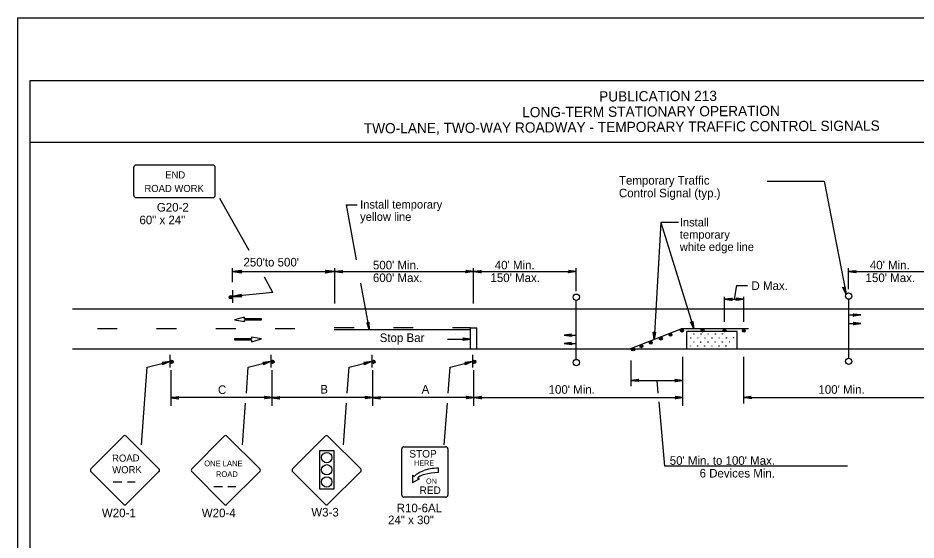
# Model space of a CAD drawing. Extents: x -14145 to -13521, y 30244 to 30661.
# Drawn here: x -13790.17 to -13768.22, y 30356.56 to 30369.31 of the extents above; entities that cross this region are included whole.
import ezdxf

# ---------------------------------------------------------------- set-up
doc = ezdxf.new("R2010")
doc.units = 0
for name, color, linetype in [('1', 7, 'Continuous'), ('10', 7, 'Continuous'), ('2', 7, 'Continuous'), ('3', 7, 'Continuous'), ('4', 7, 'Continuous'), ('61', 7, 'Continuous')]:
    doc.layers.add(name, color=color, linetype=linetype)

msp = doc.modelspace()

# ---------------------------------------------------------------- linework, layer by layer
at = {"layer": '1'}
for p, q in [((-13787.346, 30365.663), (-13787.346, 30364.975)), ((-13785.412, 30365.714), (-13787.285, 30365.714)), ((-13785.412, 30365.714), (-13787.285, 30365.714)), ((-13785.351, 30364.975), (-13785.351, 30365.663)), ((-13771.862, 30365.323), (-13770.471, 30365.323)), ((-13770.471, 30365.323), (-13769.935, 30362.561)), ((-13787.285, 30364.923), (-13785.412, 30364.923)), ((-13784.521, 30363.629), (-13785.238, 30364.895)), ((-13782.158, 30364.743), (-13781.887, 30364.743)), ((-13782.156, 30364.743), (-13781.907, 30363.402)), ((-13774.465, 30364.313), (-13774.625, 30361.456)), ((-13774.033, 30364.313), (-13774.465, 30364.313)), ((-13774.465, 30364.313), (-13773.652, 30361.715)), ((-13784.932, 30362.853), (-13784.932, 30363.195)), ((-13784.932, 30363.113), (-13782.429, 30363.113)), ((-13782.429, 30362.333), (-13782.429, 30363.195)), ((-13782.429, 30363.113), (-13779.041, 30363.113)), ((-13779.041, 30362.333), (-13779.041, 30363.195)), ((-13779.041, 30363.113), (-13776.529, 30363.113)), ((-13776.528, 30362.638), (-13776.528, 30363.194)), ((-13769.873, 30362.686), (-13769.873, 30363.195)), ((-13769.873, 30363.113), (-13767.361, 30363.113)), ((-13783.943, 30362.606), (-13784.152, 30362.976)), ((-13781.801, 30362.834), (-13781.589, 30361.693)), ((-13784.932, 30362.66), (-13784.932, 30362.348)), ((-13783.943, 30362.606), (-13784.932, 30362.504)), ((-13772.615, 30362.774), (-13772.671, 30362.436)), ((-13772.615, 30362.774), (-13772.345, 30362.774)), ((-13772.906, 30361.885), (-13772.906, 30362.5)), ((-13772.906, 30362.436), (-13772.436, 30362.436)), ((-13772.436, 30361.885), (-13772.436, 30362.5)), ((-13788.844, 30362.207), (-13759.76, 30362.207)), ((-13784.638, 30362.004), (-13784.88, 30361.938)), ((-13784.88, 30361.938), (-13784.636, 30361.892)), ((-13784.638, 30361.959), (-13784.638, 30362.004)), ((-13784.222, 30361.959), (-13784.638, 30361.959)), ((-13784.636, 30361.892), (-13784.636, 30361.937)), ((-13784.636, 30361.937), (-13784.222, 30361.937)), ((-13784.222, 30361.937), (-13784.222, 30361.959)), ((-13787.746, 30361.715), (-13788.232, 30361.715)), ((-13786.299, 30361.715), (-13786.785, 30361.715)), ((-13784.852, 30361.715), (-13785.338, 30361.715)), ((-13783.405, 30361.715), (-13783.891, 30361.715)), ((-13781.958, 30361.737), (-13782.444, 30361.737)), ((-13780.511, 30361.737), (-13780.997, 30361.737)), ((-13779.113, 30361.737), (-13779.55, 30361.737)), ((-13779.113, 30361.228), (-13779.113, 30361.737)), ((-13779.113, 30361.737), (-13778.957, 30361.737)), ((-13778.957, 30361.228), (-13778.957, 30361.737)), ((-13775.217, 30361.223), (-13773.965, 30361.715)), ((-13772.318, 30361.715), (-13773.965, 30361.715)), ((-13784.222, 30361.467), (-13784.466, 30361.514)), ((-13784.466, 30361.514), (-13784.466, 30361.468)), ((-13779.113, 30361.693), (-13782.442, 30361.693)), ((-13772.598, 30361.649), (-13773.822, 30361.649)), ((-13773.822, 30361.223), (-13773.822, 30361.649)), ((-13772.598, 30361.223), (-13772.598, 30361.649)), ((-13784.466, 30361.468), (-13784.88, 30361.468)), ((-13784.88, 30361.468), (-13784.88, 30361.446)), ((-13784.88, 30361.446), (-13784.463, 30361.446)), ((-13784.463, 30361.401), (-13784.222, 30361.467)), ((-13784.463, 30361.446), (-13784.463, 30361.401)), ((-13779.678, 30361.462), (-13779.113, 30361.462)), ((-13788.844, 30361.223), (-13759.76, 30361.223)), ((-13786.459, 30361.084), (-13786.459, 30360.772)), ((-13783.993, 30361.084), (-13783.993, 30360.772)), ((-13783.993, 30361.084), (-13783.993, 30360.772)), ((-13781.527, 30361.084), (-13781.527, 30360.772)), ((-13781.527, 30361.084), (-13781.527, 30360.772)), ((-13779.061, 30361.084), (-13779.061, 30360.772)), ((-13779.061, 30361.084), (-13779.061, 30360.772)), ((-13787.012, 30360.777), (-13786.465, 30360.917)), ((-13784.546, 30360.777), (-13783.999, 30360.917)), ((-13782.08, 30360.777), (-13781.533, 30360.917)), ((-13779.614, 30360.777), (-13779.067, 30360.917)), ((-13775.184, 30360.314), (-13775.184, 30360.94)), ((-13773.923, 30359.835), (-13773.923, 30361.029)), ((-13772.436, 30359.889), (-13772.436, 30361.035)), ((-13787.151, 30358.886), (-13787.012, 30360.777)), ((-13786.429, 30359.835), (-13786.429, 30360.709)), ((-13784.592, 30360.143), (-13784.546, 30360.777)), ((-13783.963, 30359.835), (-13783.963, 30360.709)), ((-13782.126, 30360.143), (-13782.08, 30360.777)), ((-13781.497, 30359.835), (-13781.497, 30360.709)), ((-13779.66, 30360.143), (-13779.614, 30360.777)), ((-13779.031, 30359.835), (-13779.031, 30360.709)), ((-13775.184, 30360.455), (-13773.929, 30360.455)), ((-13783.963, 30360.039), (-13786.429, 30360.039)), ((-13781.497, 30360.039), (-13783.963, 30360.039)), ((-13779.031, 30360.039), (-13781.497, 30360.039)), ((-13779.031, 30360.039), (-13773.923, 30360.039)), ((-13772.436, 30360.039), (-13767.328, 30360.039)), ((-13784.685, 30358.886), (-13784.61, 30359.9)), ((-13782.219, 30358.886), (-13782.144, 30359.9)), ((-13779.753, 30358.886), (-13779.678, 30359.9)), ((-13787.597, 30359.096), (-13788.392, 30358.293)), ((-13786.728, 30358.293), (-13787.531, 30359.096)), ((-13785.131, 30359.096), (-13785.926, 30358.293)), ((-13784.262, 30358.293), (-13785.065, 30359.096)), ((-13782.665, 30359.096), (-13783.46, 30358.293)), ((-13781.796, 30358.293), (-13782.599, 30359.096)), ((-13782.799, 30357.803), (-13782.799, 30358.741)), ((-13782.799, 30358.741), (-13782.457, 30358.741)), ((-13782.457, 30358.741), (-13782.457, 30357.803)), ((-13780.794, 30357.651), (-13780.794, 30358.787)), ((-13780.739, 30358.834), (-13779.721, 30358.834)), ((-13779.667, 30358.787), (-13779.667, 30357.651)), ((-13788.392, 30358.227), (-13787.597, 30357.432)), ((-13787.531, 30357.432), (-13786.728, 30358.227)), ((-13785.926, 30358.227), (-13785.131, 30357.432)), ((-13785.065, 30357.432), (-13784.262, 30358.227)), ((-13783.46, 30358.227), (-13782.665, 30357.432)), ((-13782.599, 30357.432), (-13781.796, 30358.227)), ((-13779.896, 30358.206), (-13779.898, 30358.317)), ((-13787.843, 30357.979), (-13787.633, 30357.979)), ((-13787.5, 30357.979), (-13787.307, 30357.979)), ((-13780.531, 30358.134), (-13780.531, 30357.963)), ((-13780.486, 30358.112), (-13780.531, 30358.134)), ((-13780.531, 30357.963), (-13780.36, 30358.049)), ((-13780.36, 30358.049), (-13780.407, 30358.072)), ((-13785.388, 30357.863), (-13785.177, 30357.863)), ((-13785.045, 30357.863), (-13784.852, 30357.863)), ((-13782.457, 30357.803), (-13782.799, 30357.803)), ((-13779.721, 30357.604), (-13780.739, 30357.604))]:
    msp.add_line(p, q, dxfattribs=at)
for points in [[(-13782.255, 30363.089), (-13782.261, 30363.101), (-13782.429, 30363.113), (-13782.255, 30363.089), (-13782.243, 30363.083), (-13782.429, 30363.113), (-13782.261, 30363.119), (-13782.255, 30363.131), (-13782.429, 30363.113), (-13782.243, 30363.143), (-13782.255, 30363.131)], [(-13779.221, 30363.137), (-13779.215, 30363.125), (-13779.041, 30363.113), (-13779.221, 30363.137), (-13779.227, 30363.143), (-13779.041, 30363.113), (-13779.215, 30363.107), (-13779.221, 30363.095), (-13779.041, 30363.113), (-13779.227, 30363.083), (-13779.221, 30363.095)], [(-13778.867, 30363.089), (-13778.873, 30363.101), (-13779.041, 30363.113), (-13778.867, 30363.089), (-13778.855, 30363.083), (-13779.041, 30363.113), (-13778.873, 30363.119), (-13778.867, 30363.131), (-13779.041, 30363.113), (-13778.855, 30363.143), (-13778.867, 30363.131)], [(-13776.709, 30363.137), (-13776.703, 30363.125), (-13776.529, 30363.113), (-13776.709, 30363.137), (-13776.715, 30363.143), (-13776.529, 30363.113), (-13776.703, 30363.107), (-13776.709, 30363.095), (-13776.529, 30363.113), (-13776.715, 30363.083), (-13776.709, 30363.095)], [(-13769.699, 30363.089), (-13769.705, 30363.101), (-13769.873, 30363.113), (-13769.699, 30363.089), (-13769.687, 30363.083), (-13769.873, 30363.113), (-13769.705, 30363.119), (-13769.699, 30363.131), (-13769.873, 30363.113), (-13769.687, 30363.143), (-13769.699, 30363.131)], [(-13769.971, 30362.739), (-13769.982, 30362.726), (-13769.935, 30362.561), (-13769.971, 30362.739), (-13769.966, 30362.746), (-13769.935, 30362.561), (-13770, 30362.719), (-13770.013, 30362.725), (-13769.935, 30362.561), (-13770.025, 30362.729), (-13770.013, 30362.725)], [(-13772.732, 30362.412), (-13772.738, 30362.424), (-13772.906, 30362.436), (-13772.732, 30362.412), (-13772.72, 30362.406), (-13772.906, 30362.436), (-13772.738, 30362.442), (-13772.732, 30362.454), (-13772.906, 30362.436), (-13772.72, 30362.466), (-13772.732, 30362.454)], [(-13772.616, 30362.46), (-13772.61, 30362.448), (-13772.436, 30362.436), (-13772.616, 30362.46), (-13772.622, 30362.466), (-13772.436, 30362.436), (-13772.61, 30362.43), (-13772.616, 30362.418), (-13772.436, 30362.436), (-13772.622, 30362.406), (-13772.616, 30362.418)], [(-13769.752, 30362.077), (-13769.74, 30362.059), (-13769.572, 30362.053), (-13769.752, 30362.077), (-13769.758, 30362.083), (-13769.572, 30362.053), (-13769.74, 30362.047), (-13769.746, 30362.029), (-13769.572, 30362.053), (-13769.758, 30362.023), (-13769.746, 30362.029)], [(-13781.64, 30361.861), (-13781.627, 30361.856), (-13781.589, 30361.693), (-13781.64, 30361.861), (-13781.649, 30361.863), (-13781.589, 30361.693), (-13781.608, 30361.857), (-13781.599, 30361.869), (-13781.589, 30361.693), (-13781.592, 30361.876), (-13781.599, 30361.869)], [(-13773.683, 30361.887), (-13773.694, 30361.875), (-13773.652, 30361.715), (-13773.683, 30361.887), (-13773.679, 30361.892), (-13773.652, 30361.715), (-13773.711, 30361.868), (-13773.724, 30361.874), (-13773.652, 30361.715), (-13773.735, 30361.877), (-13773.724, 30361.874)], [(-13769.752, 30361.873), (-13769.74, 30361.855), (-13769.572, 30361.849), (-13769.752, 30361.873), (-13769.758, 30361.879), (-13769.572, 30361.849), (-13769.74, 30361.843), (-13769.746, 30361.825), (-13769.572, 30361.849), (-13769.758, 30361.819), (-13769.746, 30361.825)], [(-13779.294, 30361.484), (-13779.285, 30361.469), (-13779.113, 30361.462), (-13779.294, 30361.484), (-13779.298, 30361.491), (-13779.113, 30361.462), (-13779.283, 30361.45), (-13779.293, 30361.44), (-13779.113, 30361.462), (-13779.301, 30361.429), (-13779.293, 30361.44)], [(-13776.647, 30361.54), (-13776.659, 30361.552), (-13776.827, 30361.558), (-13776.647, 30361.54), (-13776.641, 30361.528), (-13776.827, 30361.558), (-13776.659, 30361.57), (-13776.653, 30361.582), (-13776.827, 30361.558), (-13776.641, 30361.588), (-13776.653, 30361.582)], [(-13774.594, 30361.628), (-13774.608, 30361.62), (-13774.625, 30361.456), (-13774.594, 30361.628), (-13774.588, 30361.631), (-13774.625, 30361.456), (-13774.627, 30361.62), (-13774.637, 30361.63), (-13774.625, 30361.456), (-13774.646, 30361.637), (-13774.637, 30361.63)], [(-13776.647, 30361.336), (-13776.659, 30361.348), (-13776.827, 30361.354), (-13776.647, 30361.336), (-13776.641, 30361.324), (-13776.827, 30361.354), (-13776.659, 30361.366), (-13776.653, 30361.378), (-13776.827, 30361.354), (-13776.641, 30361.384), (-13776.653, 30361.378)], [(-13786.645, 30360.893), (-13786.633, 30360.881), (-13786.465, 30360.917), (-13786.645, 30360.893), (-13786.651, 30360.899), (-13786.465, 30360.917), (-13786.627, 30360.863), (-13786.633, 30360.851), (-13786.465, 30360.917), (-13786.639, 30360.839), (-13786.633, 30360.851)], [(-13784.179, 30360.893), (-13784.167, 30360.881), (-13783.999, 30360.917), (-13784.179, 30360.893), (-13784.185, 30360.899), (-13783.999, 30360.917), (-13784.161, 30360.863), (-13784.167, 30360.851), (-13783.999, 30360.917), (-13784.173, 30360.839), (-13784.167, 30360.851)], [(-13781.713, 30360.893), (-13781.701, 30360.881), (-13781.533, 30360.917), (-13781.713, 30360.893), (-13781.719, 30360.899), (-13781.533, 30360.917), (-13781.695, 30360.863), (-13781.701, 30360.851), (-13781.533, 30360.917), (-13781.707, 30360.839), (-13781.701, 30360.851)], [(-13779.247, 30360.893), (-13779.235, 30360.881), (-13779.067, 30360.917), (-13779.247, 30360.893), (-13779.253, 30360.899), (-13779.067, 30360.917), (-13779.229, 30360.863), (-13779.235, 30360.851), (-13779.067, 30360.917), (-13779.241, 30360.839), (-13779.235, 30360.851)], [(-13775.004, 30360.437), (-13775.016, 30360.449), (-13775.184, 30360.455), (-13775.004, 30360.437), (-13774.998, 30360.425), (-13775.184, 30360.455), (-13775.016, 30360.467), (-13775.01, 30360.479), (-13775.184, 30360.455), (-13774.998, 30360.485), (-13775.01, 30360.479)], [(-13774.525, 30360.141), (-13774.553, 30360.455)], [(-13774.109, 30360.479), (-13774.097, 30360.461), (-13773.929, 30360.455), (-13774.109, 30360.479), (-13774.115, 30360.485), (-13773.929, 30360.455), (-13774.097, 30360.449), (-13774.103, 30360.431), (-13773.929, 30360.455), (-13774.115, 30360.425), (-13774.103, 30360.431)], [(-13786.249, 30360.009), (-13786.255, 30360.021), (-13786.429, 30360.033), (-13786.249, 30360.009), (-13786.243, 30360.003), (-13786.429, 30360.033), (-13786.255, 30360.039), (-13786.249, 30360.051), (-13786.429, 30360.033), (-13786.243, 30360.063), (-13786.249, 30360.051)], [(-13784.143, 30360.063), (-13784.137, 30360.045), (-13783.963, 30360.039), (-13784.143, 30360.063), (-13784.149, 30360.069), (-13783.963, 30360.039), (-13784.137, 30360.033), (-13784.143, 30360.015), (-13783.963, 30360.039), (-13784.149, 30360.009), (-13784.143, 30360.015)], [(-13783.783, 30360.009), (-13783.789, 30360.021), (-13783.963, 30360.033), (-13783.783, 30360.009), (-13783.777, 30360.003), (-13783.963, 30360.033), (-13783.789, 30360.039), (-13783.783, 30360.051), (-13783.963, 30360.033), (-13783.777, 30360.063), (-13783.783, 30360.051)], [(-13781.677, 30360.063), (-13781.671, 30360.045), (-13781.497, 30360.039), (-13781.677, 30360.063), (-13781.683, 30360.069), (-13781.497, 30360.039), (-13781.671, 30360.033), (-13781.677, 30360.015), (-13781.497, 30360.039), (-13781.683, 30360.009), (-13781.677, 30360.015)], [(-13781.317, 30360.009), (-13781.323, 30360.021), (-13781.497, 30360.033), (-13781.317, 30360.009), (-13781.311, 30360.003), (-13781.497, 30360.033), (-13781.323, 30360.039), (-13781.317, 30360.051), (-13781.497, 30360.033), (-13781.311, 30360.063), (-13781.317, 30360.051)], [(-13779.211, 30360.063), (-13779.205, 30360.045), (-13779.031, 30360.039), (-13779.211, 30360.063), (-13779.217, 30360.069), (-13779.031, 30360.039), (-13779.205, 30360.033), (-13779.211, 30360.015), (-13779.031, 30360.039), (-13779.217, 30360.009), (-13779.211, 30360.015)], [(-13778.857, 30360.015), (-13778.863, 30360.027), (-13779.031, 30360.039), (-13778.857, 30360.015), (-13778.845, 30360.009), (-13779.031, 30360.039), (-13778.863, 30360.045), (-13778.857, 30360.057), (-13779.031, 30360.039), (-13778.845, 30360.069), (-13778.857, 30360.057)], [(-13774.103, 30360.063), (-13774.091, 30360.045), (-13773.923, 30360.039), (-13774.103, 30360.063), (-13774.109, 30360.069), (-13773.923, 30360.039), (-13774.091, 30360.033), (-13774.097, 30360.015), (-13773.923, 30360.039), (-13774.109, 30360.009), (-13774.097, 30360.015)], [(-13772.256, 30360.021), (-13772.268, 30360.033), (-13772.436, 30360.039), (-13772.256, 30360.021), (-13772.25, 30360.009), (-13772.436, 30360.039), (-13772.268, 30360.051), (-13772.262, 30360.063), (-13772.436, 30360.039), (-13772.25, 30360.069), (-13772.262, 30360.063)], [(-13769.902, 30358.359), (-13774.365, 30358.359), (-13774.506, 30359.936)]]:
    msp.add_lwpolyline(points, dxfattribs=at)
for centre, radius in [((-13784.973, 30362.487), 0.0408), ((-13774.462, 30361.479), 0.038), ((-13774.463, 30361.475), 0.0155), ((-13774.225, 30361.569), 0.0346), ((-13774.224, 30361.565), 0.0101), ((-13773.943, 30361.673), 0.037), ((-13773.943, 30361.673), 0.037), ((-13773.946, 30361.671), 0.0172), ((-13773.946, 30361.671), 0.0172), ((-13773.731, 30361.489), 0.00272), ((-13773.651, 30361.587), 0.00272), ((-13773.556, 30361.491), 0.00272), ((-13773.479, 30361.588), 0.00272), ((-13773.443, 30361.673), 0.037), ((-13773.446, 30361.671), 0.0172), ((-13773.385, 30361.489), 0.00272), ((-13773.304, 30361.589), 0.00272), ((-13773.209, 30361.491), 0.00272), ((-13773.13, 30361.588), 0.00272), ((-13773.035, 30361.49), 0.00272), ((-13772.958, 30361.59), 0.00272), ((-13772.904, 30361.675), 0.0353), ((-13772.9, 30361.676), 0.014), ((-13772.863, 30361.495), 0.00272), ((-13772.862, 30361.492), 0.00272), ((-13772.783, 30361.593), 0.00272), ((-13772.688, 30361.497), 0.00272), ((-13772.435, 30361.667), 0.0331), ((-13772.436, 30361.668), 0.012), ((-13774.935, 30361.291), 0.037), ((-13774.934, 30361.289), 0.0194), ((-13774.708, 30361.378), 0.036), ((-13774.711, 30361.384), 0.0161), ((-13773.736, 30361.294), 0.00272), ((-13773.656, 30361.391), 0.00272), ((-13773.561, 30361.295), 0.00272), ((-13773.485, 30361.391), 0.00272), ((-13773.388, 30361.295), 0.00272), ((-13773.308, 30361.392), 0.00272), ((-13773.214, 30361.296), 0.00272), ((-13773.135, 30361.392), 0.00272), ((-13773.041, 30361.297), 0.00272), ((-13772.96, 30361.393), 0.00272), ((-13772.869, 30361.3), 0.00272), ((-13772.867, 30361.297), 0.00272), ((-13772.789, 30361.397), 0.00272), ((-13772.694, 30361.301), 0.00272), ((-13775.137, 30361.213), 0.0379), ((-13775.136, 30361.213), 0.014), ((-13786.419, 30360.911), 0.0408), ((-13783.953, 30360.911), 0.0408), ((-13781.487, 30360.911), 0.0408), ((-13779.021, 30360.911), 0.0408), ((-13782.628, 30358.57), 0.126), ((-13782.628, 30358.272), 0.126), ((-13782.628, 30357.975), 0.126)]:
    msp.add_circle(centre, radius, dxfattribs=at)
for centre, radius, start, end in [((-13784.968, 30362.495), 0.0214, 355.7499, 350.479), ((-13786.424, 30360.919), 0.0214, 189.521, 184.2501), ((-13783.958, 30360.919), 0.0214, 189.521, 184.2501), ((-13781.492, 30360.919), 0.0214, 189.521, 184.2501), ((-13779.026, 30360.919), 0.0214, 189.521, 184.2501), ((-13787.563, 30359.062), 0.0465, 45, 135), ((-13785.098, 30359.062), 0.0465, 45, 135), ((-13782.632, 30359.062), 0.0465, 45, 135), ((-13788.358, 30358.259), 0.0465, 135, 225), ((-13786.76, 30358.259), 0.0465, 315, 45), ((-13785.893, 30358.26), 0.0465, 135, 225), ((-13784.295, 30358.259), 0.0465, 315, 45), ((-13783.427, 30358.26), 0.0465, 135, 225), ((-13781.829, 30358.259), 0.0465, 315, 45), ((-13787.563, 30357.464), 0.0465, 225, 315), ((-13785.098, 30357.464), 0.0465, 225, 315), ((-13782.632, 30357.464), 0.0465, 225, 315)]:
    msp.add_arc(centre, radius, start, end, dxfattribs=at)
for centre, major_axis, ratio, start_param, end_param in [((-13787.284, 30365.661), (0.0609, 0), 0.839899, 1.570796, 3.141593), ((-13785.411, 30365.661), (-0.0609, 0), 0.839899, 3.141593, 4.712389), ((-13787.284, 30364.973), (0.0609, 0), 0.839899, 3.141593, 4.712389), ((-13785.411, 30364.973), (-0.0609, 0), 0.839899, 1.570796, 3.141593), ((-13780.739, 30358.787), (-0.0541, 0), 0.866667, 4.712389, 6.283185), ((-13779.721, 30358.787), (-0.0541, 0), 0.866667, 3.141593, 4.712389), ((-13779.862, 30358.306), (0.632, 0.211), 0.13767, 2.24751, 2.61166), ((-13779.887, 30358.068), (0.526, 0.021), 0.259792, 1.574563, 2.966983), ((-13779.854, 30358.095), (0.626, 0.024), 0.356316, 1.625555, 2.277861), ((-13779.887, 30358.068), (0.626, 0.024), 0.356316, 2.688881, 2.833949), ((-13780.246, 30357.97), (-0.29, 0), 0.866667, 5.239865, 5.534055), ((-13780.739, 30357.651), (0.0541, 0), 0.866667, 3.141593, 4.712389), ((-13779.721, 30357.651), (0.0541, 0), 0.866667, 4.712389, 6.283185)]:
    msp.add_ellipse(centre, major_axis=major_axis, ratio=ratio, start_param=start_param, end_param=end_param, dxfattribs=at)
at = {"layer": '10'}
for p, q in [((-13789.874, 30367.777), (-13758.422, 30367.777)), ((-13789.874, 30345.207), (-13789.874, 30367.777)), ((-13789.874, 30366.277), (-13758.422, 30366.277))]:
    msp.add_line(p, q, dxfattribs=at)
at = {"layer": '2'}
for p, q in [((-13776.527, 30360.97), (-13776.527, 30362.416)), ((-13769.872, 30362.437), (-13769.872, 30360.991)), ((-13769.872, 30362.053), (-13769.572, 30362.053)), ((-13769.872, 30361.849), (-13769.572, 30361.849)), ((-13776.827, 30361.558), (-13776.527, 30361.558)), ((-13776.827, 30361.354), (-13776.527, 30361.354))]:
    msp.add_line(p, q, dxfattribs=at)
for centre in [(-13769.872, 30362.515), (-13776.527, 30362.487), (-13776.527, 30360.892), (-13769.872, 30360.92)]:
    msp.add_circle(centre, 0.0774, dxfattribs=at)
at = {"layer": '3'}
for points in [[(-13784.714, 30363.086), (-13784.722, 30363.102), (-13784.932, 30363.113), (-13784.714, 30363.086), (-13784.703, 30363.077), (-13784.932, 30363.113), (-13784.722, 30363.124), (-13784.714, 30363.139), (-13784.932, 30363.113), (-13784.703, 30363.15), (-13784.714, 30363.139)], [(-13782.647, 30363.141), (-13782.639, 30363.125), (-13782.429, 30363.113), (-13782.647, 30363.141), (-13782.658, 30363.15), (-13782.429, 30363.113), (-13782.639, 30363.103), (-13782.646, 30363.087), (-13782.429, 30363.113), (-13782.658, 30363.077), (-13782.646, 30363.087)], [(-13784.712, 30362.5), (-13784.722, 30362.514), (-13784.932, 30362.504), (-13784.712, 30362.5), (-13784.7, 30362.491), (-13784.932, 30362.504), (-13784.724, 30362.536), (-13784.718, 30362.553), (-13784.932, 30362.504), (-13784.707, 30362.564), (-13784.718, 30362.553)]]:
    msp.add_lwpolyline(points, dxfattribs=at)
at = {"layer": '61'}
msp.add_lwpolyline([(-13790.174, 30369.307), (-13757.174, 30369.307), (-13757.174, 30343.807), (-13790.174, 30343.807)], close=True, dxfattribs=at)

# ---------------------------------------------------------------- texts
at = {"layer": '1'}
for s, height, p in [('END', 0.173, (-13786.574, 30365.388)), ('ROAD WORK', 0.173, (-13787.083, 30365.057)), ('STOP', 0.1838, (-13780.608, 30358.572)), ('ONE LANE', 0.1386, (-13785.621, 30358.36)), ('HERE', 0.1268, (-13780.489, 30358.376)), ('ROAD', 0.1389, (-13785.336, 30358.097)), ('ON', 0.1268, (-13780.2, 30357.933)), ('RED', 0.1838, (-13780.357, 30357.682))]:
    msp.add_text(s, height=height, dxfattribs=at).set_placement(p)
for s, height, rotation, p in [('ROAD', 0.1735, 0.7566, (-13787.872, 30358.468)), ('WORK', 0.1733, 0.7588, (-13787.868, 30358.183))]:
    msp.add_text(s, height=height, rotation=rotation, dxfattribs=at).set_placement(p)
at = {"layer": '2'}
for s, height, p in [('Temporary Traffic ', 0.21, (-13775.485, 30365.237)), ('Control Signal (typ.)', 0.21, (-13775.485, 30364.927)), ('G20-2', 0.21, (-13786.78, 30364.579)), ('Install temporary', 0.20313, (-13781.811, 30364.652)), ('yellow line', 0.20313, (-13781.811, 30364.352)), ('60" x 24"', 0.21, (-13787.204, 30364.269)), ('Install', 0.2031, (-13773.997, 30364.216)), ('temporary', 0.2031, (-13773.997, 30363.917)), ('white edge line', 0.20313, (-13773.997, 30363.617)), ("250'to 500'", 0.21, (-13784.662, 30363.238)), ("500' Min.", 0.21, (-13781.498, 30363.167)), ("40' Min.", 0.21, (-13778.52, 30363.167)), ("40' Min.", 0.21, (-13769.352, 30363.167)), ("600' Max.", 0.21, (-13781.498, 30362.857)), ("150' Max.", 0.21, (-13778.625, 30362.857)), ("150' Max.", 0.21, (-13769.457, 30362.857)), ('D Max.', 0.21, (-13772.246, 30362.664)), ('Stop Bar', 0.21, (-13781.332, 30361.393)), ('C', 0.21, (-13785.285, 30360.123)), ('B', 0.21, (-13782.784, 30360.135)), ('A', 0.21, (-13780.308, 30360.135)), ("100' Min.", 0.21, (-13777.204, 30360.129)), ("100' Min.", 0.21, (-13770.609, 30360.129)), ("50' Min. to 100' Max.", 0.21, (-13774.244, 30358.394)), ('6 Devices Min.', 0.21, (-13773.514, 30358.084)), ('W20-1', 0.21, (-13788.122, 30357.114)), ('W20-4', 0.21, (-13785.68, 30357.114)), ('W3-3', 0.21, (-13783.004, 30357.132)), ('R10-6AL', 0.21, (-13780.917, 30357.235)), ('24" x 30"', 0.21, (-13781.128, 30356.944))]:
    msp.add_text(s, height=height, dxfattribs=at).set_placement(p)
at = {"layer": '4'}
for s, p in [('PUBLICATION 213', (-13775.969, 30367.266)), ('LONG-TERM STATIONARY OPERATION', (-13777.849, 30366.881)), ('TWO-LANE, TWO-WAY ROADWAY - TEMPORARY TRAFFIC CONTROL SIGNALS', (-13781.721, 30366.486))]:
    msp.add_text(s, height=0.25, rotation=0.31, dxfattribs=at).set_placement(p)

doc.saveas('drawing.dxf')
